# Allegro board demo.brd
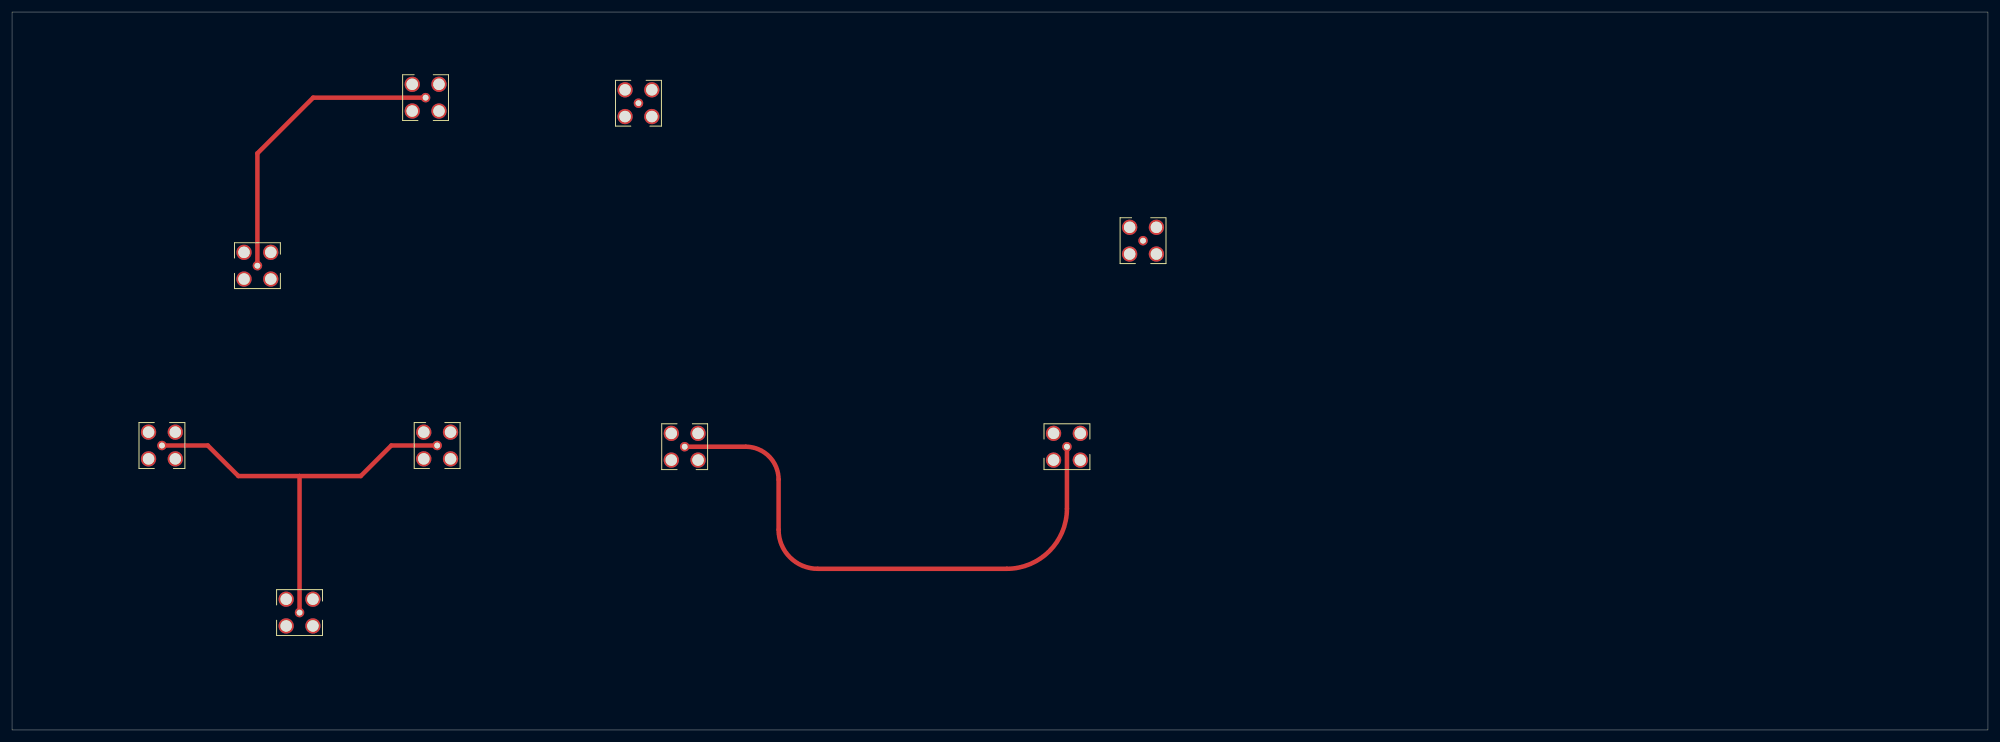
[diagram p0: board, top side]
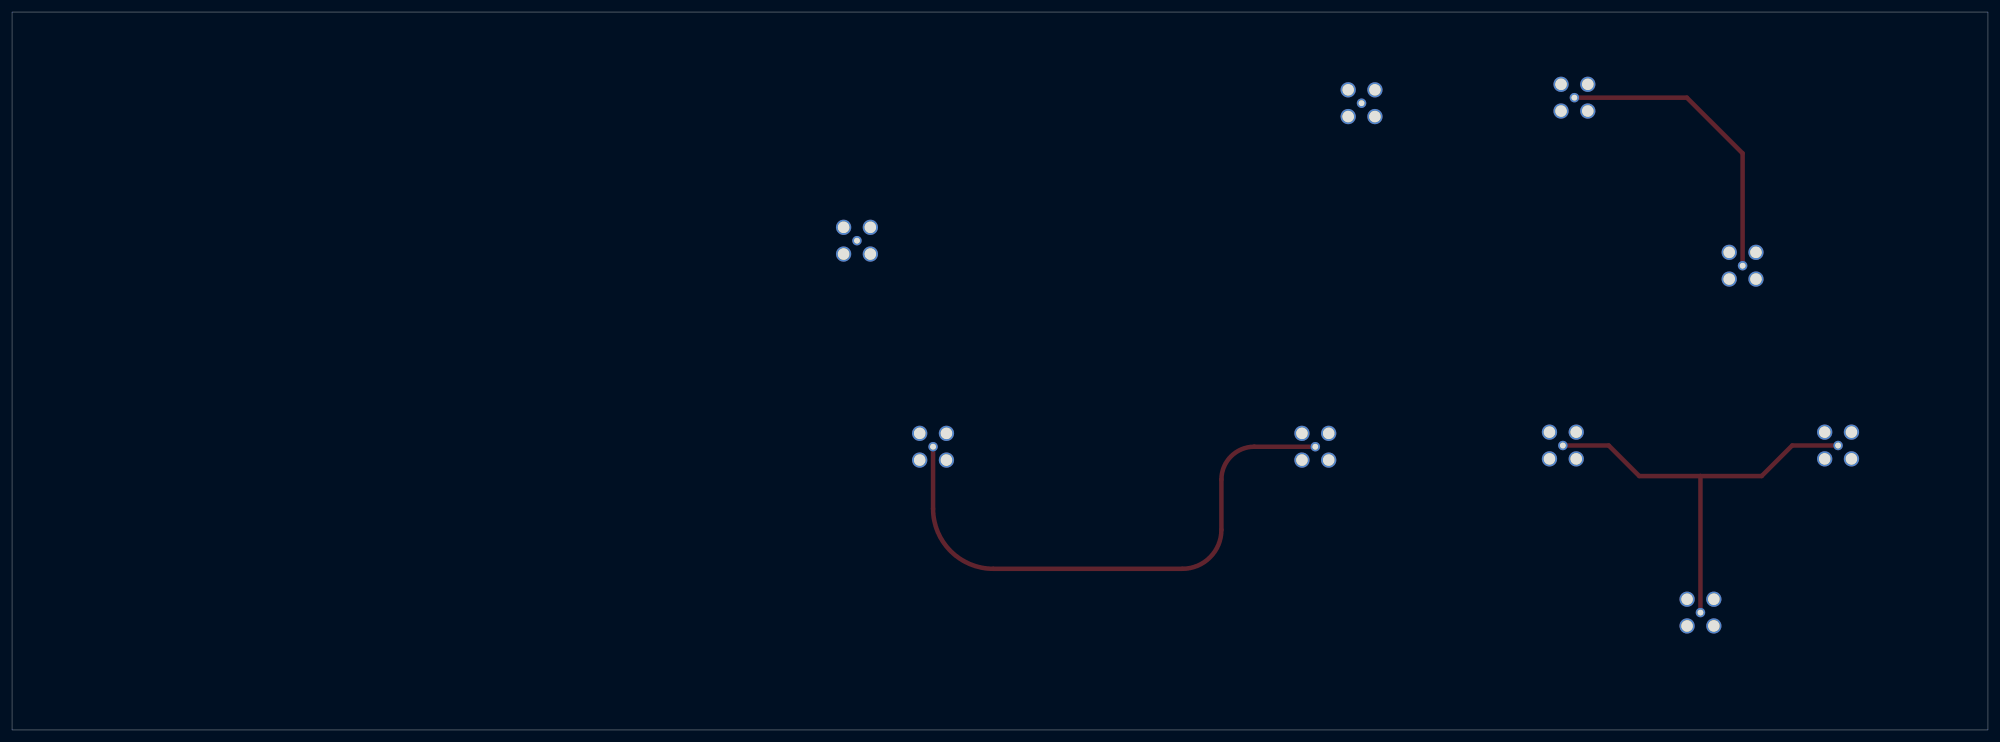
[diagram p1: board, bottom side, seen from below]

Outline 328.24 x 119.38 mm; copper layers: TOP, L2, L3, L4, L5, BOTTOM. Coordinates in mm from the lower left corner of the outline.
Outline path: 0,119.38 0,0 328.24,0 328.24,119.38 0,119.38

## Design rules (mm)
constraint set DEFAULT: min track width 0.127

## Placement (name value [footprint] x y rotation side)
J1  -  [BNC]  111.74 47.1 180 top
J2  -  [BNC]  175.24 47.1 90 top
J3  -  [BNC]  24.9 47.3 180 top
J4  -  [BNC]  70.62 47.3 0 top
J5  -  [BNC]  47.76 19.52 270 top
J6  -  [BNC]  104.06 104.22 180 top
J7  -  [BNC]  187.88 81.36 0 top
J8  -  [BNC]  40.76 77.2 270 top
J9  -  [BNC]  68.7 105.14 0 top

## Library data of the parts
J1-J9 = DUMMY_BNC

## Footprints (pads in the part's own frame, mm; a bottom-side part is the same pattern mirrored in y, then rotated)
BNC
  round 1.575 hole 0.965: 1(0,0)
  round 2.54 hole 1.905: 2(-2.223,2.223) 3(-2.223,-2.223) 4(2.223,2.223) 5(2.223,-2.223)

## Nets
GND: J1.2 J1.3 J1.4 J1.5 J2.2 J2.3 J2.4 J2.5 J3.2 J3.3 J3.4 J3.5 J4.2 J4.3 J4.4 J4.5 J5.2 J5.3 J5.4 J5.5 J6.2 J6.3 J6.4 J6.5 J7.2 J7.3 J7.4 J7.5 J8.2 J8.3 J8.4 J8.5 J9.2 J9.3 J9.4 J9.5
SIG10: J1.1 J2.1
SIG12: J3.1 J4.1 J5.1
SIG13: J6.1 J7.1
SIG14: J8.1 J9.1

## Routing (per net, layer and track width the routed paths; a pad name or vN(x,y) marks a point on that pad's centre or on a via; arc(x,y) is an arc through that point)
SIG10: length 94.7
  TOP w0.75: J1.1 121.88,47.1 arc(125.74,45.5) 127.34,41.64 127.34,33.28 arc(129.24,28.7) 133.82,26.8 165.24,26.8 arc(172.31,29.73) 175.24,36.8 J2.1
SIG12: length 72.6
  TOP w0.75: J3.1 32.52,47.3 37.6,42.22 47.76,42.22 ; 47.76,42.22 57.92,42.22 63,47.3 J4.1 ; 47.76,42.22 J5.1
SIG14: length 50.5
  TOP w0.75: J8.1 40.76,95.88 50.02,105.14 J9.1
